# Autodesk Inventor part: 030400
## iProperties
Shininess: 69.0
Length Units: 11269
Angle Units: 11279
Time Units: 11290
Mass Units: 11284
Length Display Precision: 3
Angle Display Precision: 2
Compacted: True
Company: Pneumax S.p.A.
Part Number: 030400
Material: Default
Description: INTERMEDIO Ø4
Document SubType Name: Modellazione
Catalog Web Link: www.pneumaxspa.com
Density: 1.59
Volumn: 0.8648857994912436
Area: 17.092995283760587
PropertySet Name: Model Information
Control State: 0
Master: False
Checked Out: False
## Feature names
1. Revolution6
2. Foro6 [Hole]
3. Revolution7
4. Hole7
